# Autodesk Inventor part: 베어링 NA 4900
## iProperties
Created: 2009-02
Part Number: 베어링 NA 4900
Material: Steel, Mild
Description: 니들 롤러 베어링 - 경계 치수 및 공차
Document SubType Name: Modeling
Standard: KS B 2029
Designer: KYOUNG IL JANG
Standards Organization: KS
Language: ko-KR
Size Designation: NA 4900 - 10 x 22 x 13
Categories: <MemberInstance><Categories><Category DisplayName="샤프트 부품" InternalName="7f7aeb1f-a693-4053-b835-cee3144e0d98" Mnemonic="SHFT"><Category DisplayName="베어링" Inter
Density: 7.86 g/cm^3
Mass: 23.8214 g
Surface Area: 38.613 cm^2
Volume: 3.03071 cm^3
Company: 한국ATC센터
IsCustomPart: 0
Author: KYOUNG IL JANG
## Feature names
1. IDS_ARRAYROLLER[SIMPL:T] [Circular Pattern]
